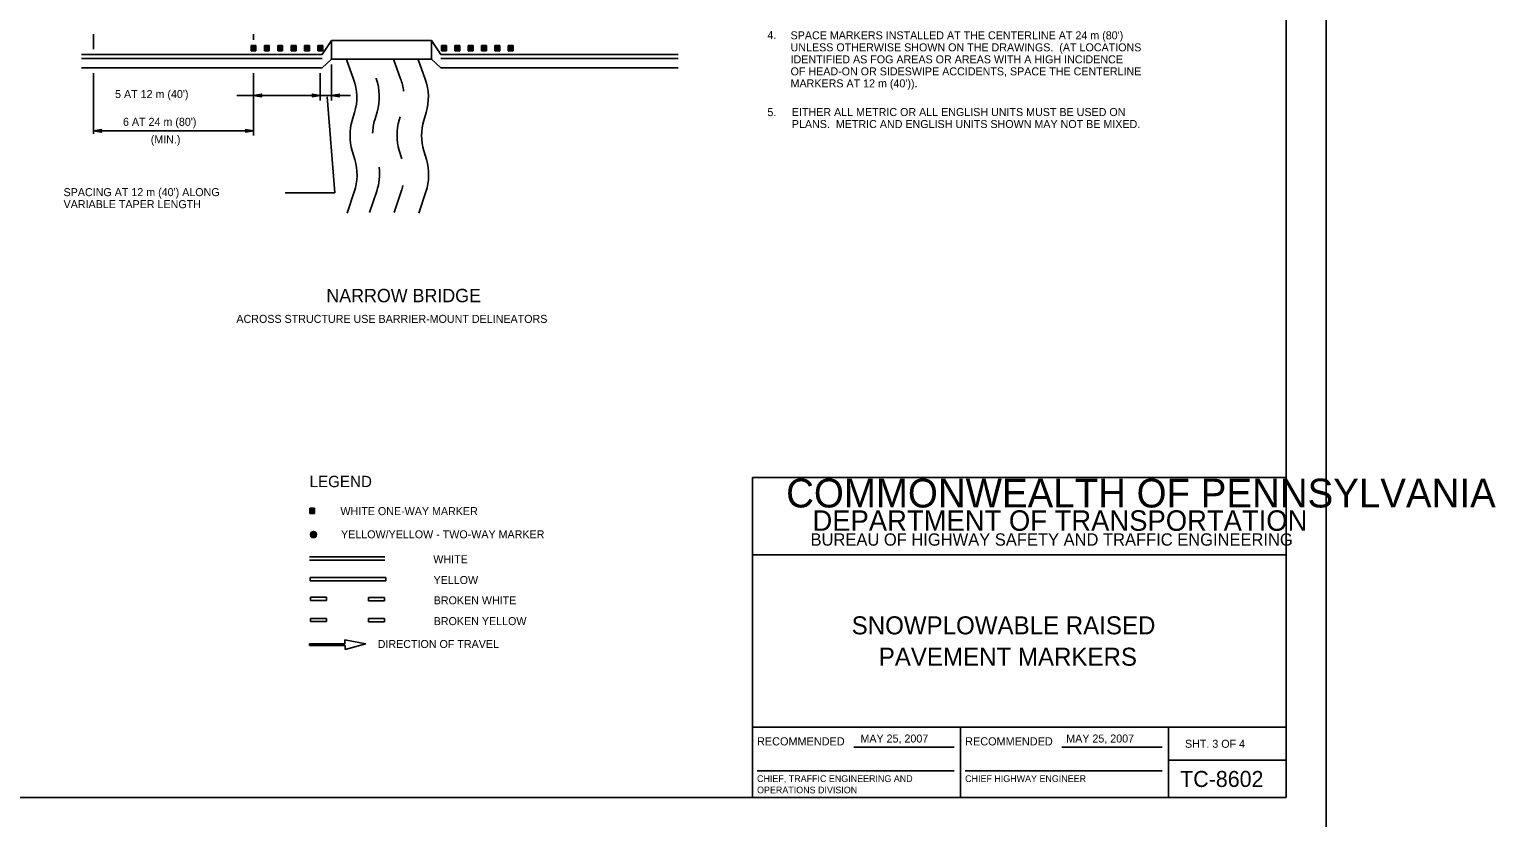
# Model space of a CAD drawing. Extents: x 639362 to 641108, y 298458 to 299646.
# Drawn here: x 640558 to 641108, y 299059 to 299355 of the extents above; entities that cross this region are included whole.
import ezdxf

# ---------------------------------------------------------------- set-up
doc = ezdxf.new("R2010")
doc.units = 0
for name, color, linetype in [('1', 7, 'Continuous'), ('2', 7, 'Continuous'), ('3', 7, 'Continuous'), ('PLT-BNDY', 7, 'Continuous')]:
    doc.layers.add(name, color=color, linetype=linetype)

# ---------------------------------------------------------------- blocks, each defined once
blk = doc.blocks.new('RARROW')
at = {"layer": '3'}
blk.add_lwpolyline([(-2.2695, 0.285), (-2.184875, 0.12075), (0, 0), (-2.2695, 0.285), (-2.38575, 0.384625), (0, 0), (-2.183125, -0.108), (-2.262875, -0.2705), (0, 0), (-2.38575, -0.379125), (-2.262875, -0.2705)], dxfattribs=at)

msp = doc.modelspace()

# ---------------------------------------------------------------- linework, layer by layer
at = {"layer": '1'}
for p, q in [((641029.31, 299066.63), (641029.31, 299630.63)), ((640829.31, 299066.63), (640829.31, 299186.63)), ((640829.31, 299186.63), (641029.31, 299186.63)), ((641029.31, 299157.63), (640829.31, 299157.63)), ((640829.31, 299093), (641029.31, 299093)), ((640907.31, 299093), (640907.31, 299066.63)), ((640985.19, 299066.63), (640985.19, 299093)), ((640867.24, 299085.57), (640904.87, 299085.57)), ((640945.24, 299085.57), (640982.87, 299085.57)), ((640985.19, 299080.63), (641029.31, 299080.63)), ((640830.99, 299076.68), (640904.87, 299076.68)), ((640908.99, 299076.68), (640982.87, 299076.68)), ((641029.31, 299066.63), (640243.31, 299066.63)), ((640243.31, 299066.63), (640829.31, 299066.63))]:
    msp.add_line(p, q, dxfattribs=at)
at = {"layer": '2'}
for p, q in [((640582.27, 299347.07), (640582.27, 299352.76)), ((640641.38, 299348.5), (640643.16, 299348.5)), ((640641.38, 299346.46), (640641.38, 299348.5)), ((640641.56, 299348.32), (640642.98, 299348.32)), ((640641.56, 299346.63), (640641.56, 299348.32)), ((640641.74, 299348.14), (640642.8, 299348.14)), ((640641.74, 299346.81), (640641.74, 299348.14)), ((640641.91, 299346.99), (640641.91, 299347.96)), ((640641.91, 299347.96), (640642.62, 299347.96)), ((640642.09, 299347.79), (640642.45, 299347.79)), ((640642.09, 299347.17), (640642.09, 299347.79)), ((640642.27, 299350.54), (640642.27, 299352.76)), ((640642.27, 299347.61), (640642.27, 299347.34)), ((640642.45, 299347.79), (640642.45, 299347.17)), ((640642.62, 299347.96), (640642.62, 299346.99)), ((640642.8, 299348.14), (640642.8, 299346.81)), ((640642.98, 299348.32), (640642.98, 299346.63)), ((640643.16, 299348.5), (640643.16, 299346.46)), ((640646.38, 299348.5), (640648.16, 299348.5)), ((640646.38, 299346.46), (640646.38, 299348.5)), ((640646.56, 299348.32), (640647.98, 299348.32)), ((640646.56, 299346.63), (640646.56, 299348.32)), ((640646.74, 299348.14), (640647.8, 299348.14)), ((640646.74, 299346.81), (640646.74, 299348.14)), ((640646.91, 299346.99), (640646.91, 299347.96)), ((640646.91, 299347.96), (640647.62, 299347.96)), ((640647.09, 299347.79), (640647.45, 299347.79)), ((640647.09, 299347.17), (640647.09, 299347.79)), ((640647.27, 299347.61), (640647.27, 299347.34)), ((640647.45, 299347.79), (640647.45, 299347.17)), ((640647.62, 299347.96), (640647.62, 299346.99)), ((640647.8, 299348.14), (640647.8, 299346.81)), ((640647.98, 299348.32), (640647.98, 299346.63)), ((640648.16, 299348.5), (640648.16, 299346.46)), ((640651.38, 299348.49), (640653.16, 299348.49)), ((640651.38, 299346.45), (640651.38, 299348.49)), ((640651.56, 299348.32), (640652.98, 299348.32)), ((640651.56, 299346.63), (640651.56, 299348.32)), ((640651.74, 299348.14), (640652.8, 299348.14)), ((640651.74, 299346.81), (640651.74, 299348.14)), ((640651.91, 299346.99), (640651.91, 299347.96)), ((640651.91, 299347.96), (640652.62, 299347.96)), ((640652.09, 299347.79), (640652.45, 299347.79)), ((640652.09, 299347.16), (640652.09, 299347.79)), ((640652.27, 299347.61), (640652.27, 299347.34)), ((640652.45, 299347.79), (640652.45, 299347.16)), ((640652.62, 299347.96), (640652.62, 299346.99)), ((640652.8, 299348.14), (640652.8, 299346.81)), ((640652.98, 299348.32), (640652.98, 299346.63)), ((640653.16, 299348.49), (640653.16, 299346.45)), ((640656.38, 299348.49), (640658.16, 299348.49)), ((640656.38, 299346.45), (640656.38, 299348.49)), ((640656.56, 299348.31), (640657.98, 299348.31)), ((640656.56, 299346.63), (640656.56, 299348.31)), ((640656.74, 299348.14), (640657.8, 299348.14)), ((640656.74, 299346.81), (640656.74, 299348.14)), ((640656.91, 299346.99), (640656.91, 299347.96)), ((640656.91, 299347.96), (640657.62, 299347.96)), ((640657.09, 299347.78), (640657.45, 299347.78)), ((640657.09, 299347.16), (640657.09, 299347.78)), ((640657.27, 299347.61), (640657.27, 299347.34)), ((640657.45, 299347.78), (640657.45, 299347.16)), ((640657.62, 299347.96), (640657.62, 299346.99)), ((640657.8, 299348.14), (640657.8, 299346.81)), ((640657.98, 299348.31), (640657.98, 299346.63)), ((640658.16, 299348.49), (640658.16, 299346.45)), ((640661.38, 299348.49), (640663.16, 299348.49)), ((640661.38, 299346.45), (640661.38, 299348.49)), ((640661.56, 299348.31), (640662.98, 299348.31)), ((640661.56, 299346.63), (640661.56, 299348.31)), ((640661.74, 299348.14), (640662.8, 299348.14)), ((640661.74, 299346.81), (640661.74, 299348.14)), ((640661.91, 299346.98), (640661.91, 299347.96)), ((640661.91, 299347.96), (640662.62, 299347.96)), ((640662.09, 299347.78), (640662.45, 299347.78)), ((640662.09, 299347.16), (640662.09, 299347.78)), ((640662.27, 299347.61), (640662.27, 299347.34)), ((640662.45, 299347.78), (640662.45, 299347.16)), ((640662.62, 299347.96), (640662.62, 299346.98)), ((640662.8, 299348.14), (640662.8, 299346.81)), ((640662.98, 299348.31), (640662.98, 299346.63)), ((640663.16, 299348.49), (640663.16, 299346.45)), ((640666.38, 299348.49), (640668.16, 299348.49)), ((640666.38, 299346.45), (640666.38, 299348.49)), ((640666.56, 299348.31), (640667.98, 299348.31)), ((640666.56, 299346.63), (640666.56, 299348.31)), ((640666.74, 299348.13), (640667.8, 299348.13)), ((640666.74, 299346.81), (640666.74, 299348.13)), ((640666.91, 299346.98), (640666.91, 299347.96)), ((640666.91, 299347.96), (640667.62, 299347.96)), ((640667.09, 299347.78), (640667.45, 299347.78)), ((640667.09, 299347.16), (640667.09, 299347.78)), ((640667.27, 299347.61), (640667.27, 299347.34)), ((640667.45, 299347.78), (640667.45, 299347.16)), ((640667.62, 299347.96), (640667.62, 299346.98)), ((640667.8, 299348.13), (640667.8, 299346.81)), ((640667.94, 299345.07), (640671.45, 299350.34)), ((640667.98, 299348.31), (640667.98, 299346.63)), ((640668.16, 299348.49), (640668.16, 299346.45)), ((640671.45, 299350.34), (640708.95, 299350.34)), ((640671.45, 299350.34), (640671.45, 299343.31)), ((640712.47, 299345.07), (640708.95, 299350.34)), ((640708.95, 299350.34), (640708.95, 299343.31)), ((640712.75, 299348.49), (640714.52, 299348.49)), ((640712.75, 299346.45), (640712.75, 299348.49)), ((640712.92, 299348.31), (640714.34, 299348.31)), ((640712.92, 299346.63), (640712.92, 299348.31)), ((640713.1, 299348.13), (640714.17, 299348.13)), ((640713.1, 299346.81), (640713.1, 299348.13)), ((640713.28, 299346.98), (640713.28, 299347.96)), ((640713.28, 299347.96), (640713.99, 299347.96)), ((640713.46, 299347.78), (640713.81, 299347.78)), ((640713.46, 299347.16), (640713.46, 299347.78)), ((640713.63, 299347.61), (640713.63, 299347.34)), ((640713.81, 299347.78), (640713.81, 299347.16)), ((640713.99, 299347.96), (640713.99, 299346.98)), ((640714.17, 299348.13), (640714.17, 299346.81)), ((640714.34, 299348.31), (640714.34, 299346.63)), ((640714.52, 299348.49), (640714.52, 299346.45)), ((640717.75, 299348.49), (640719.52, 299348.49)), ((640717.75, 299346.45), (640717.75, 299348.49)), ((640717.92, 299348.31), (640719.34, 299348.31)), ((640717.92, 299346.63), (640717.92, 299348.31)), ((640718.1, 299348.13), (640719.17, 299348.13)), ((640718.1, 299346.81), (640718.1, 299348.13)), ((640718.28, 299346.98), (640718.28, 299347.96)), ((640718.28, 299347.96), (640718.99, 299347.96)), ((640718.46, 299347.78), (640718.81, 299347.78)), ((640718.46, 299347.16), (640718.46, 299347.78)), ((640718.63, 299347.6), (640718.63, 299347.34)), ((640718.81, 299347.78), (640718.81, 299347.16)), ((640718.99, 299347.96), (640718.99, 299346.98)), ((640719.17, 299348.13), (640719.17, 299346.81)), ((640719.34, 299348.31), (640719.34, 299346.63)), ((640719.52, 299348.49), (640719.52, 299346.45)), ((640722.75, 299348.49), (640724.52, 299348.49)), ((640722.75, 299346.45), (640722.75, 299348.49)), ((640722.92, 299348.31), (640724.34, 299348.31)), ((640722.92, 299346.63), (640722.92, 299348.31)), ((640723.1, 299348.13), (640724.17, 299348.13)), ((640723.1, 299346.8), (640723.1, 299348.13)), ((640723.28, 299346.98), (640723.28, 299347.96)), ((640723.28, 299347.96), (640723.99, 299347.96)), ((640723.46, 299347.78), (640723.81, 299347.78)), ((640723.46, 299347.16), (640723.46, 299347.78)), ((640723.63, 299347.6), (640723.63, 299347.33)), ((640723.81, 299347.78), (640723.81, 299347.16)), ((640723.99, 299347.96), (640723.99, 299346.98)), ((640724.17, 299348.13), (640724.17, 299346.8)), ((640724.34, 299348.31), (640724.34, 299346.63)), ((640724.52, 299348.49), (640724.52, 299346.45)), ((640727.75, 299348.49), (640729.52, 299348.49)), ((640727.75, 299346.45), (640727.75, 299348.49)), ((640727.92, 299348.31), (640729.34, 299348.31)), ((640727.92, 299346.62), (640727.92, 299348.31)), ((640728.1, 299348.13), (640729.17, 299348.13)), ((640728.1, 299346.8), (640728.1, 299348.13)), ((640728.28, 299346.98), (640728.28, 299347.95)), ((640728.28, 299347.95), (640728.99, 299347.95)), ((640728.46, 299347.78), (640728.81, 299347.78)), ((640728.46, 299347.16), (640728.46, 299347.78)), ((640728.63, 299347.6), (640728.63, 299347.33)), ((640728.81, 299347.78), (640728.81, 299347.16)), ((640728.99, 299347.95), (640728.99, 299346.98)), ((640729.17, 299348.13), (640729.17, 299346.8)), ((640729.34, 299348.31), (640729.34, 299346.62)), ((640729.52, 299348.49), (640729.52, 299346.45)), ((640732.75, 299348.49), (640734.52, 299348.49)), ((640732.75, 299346.45), (640732.75, 299348.49)), ((640732.92, 299348.31), (640734.34, 299348.31)), ((640732.92, 299346.62), (640732.92, 299348.31)), ((640733.1, 299348.13), (640734.17, 299348.13)), ((640733.1, 299346.8), (640733.1, 299348.13)), ((640733.28, 299346.98), (640733.28, 299347.95)), ((640733.28, 299347.95), (640733.99, 299347.95)), ((640733.46, 299347.78), (640733.81, 299347.78)), ((640733.46, 299347.16), (640733.46, 299347.78)), ((640733.63, 299347.6), (640733.63, 299347.33)), ((640733.81, 299347.78), (640733.81, 299347.16)), ((640733.99, 299347.95), (640733.99, 299346.98)), ((640734.17, 299348.13), (640734.17, 299346.8)), ((640734.34, 299348.31), (640734.34, 299346.62)), ((640734.52, 299348.49), (640734.52, 299346.45)), ((640737.75, 299348.48), (640739.52, 299348.48)), ((640737.75, 299346.44), (640737.75, 299348.48)), ((640737.92, 299348.31), (640739.34, 299348.31)), ((640737.92, 299346.62), (640737.92, 299348.31)), ((640738.1, 299348.13), (640739.17, 299348.13)), ((640738.1, 299346.8), (640738.1, 299348.13)), ((640738.28, 299346.98), (640738.28, 299347.95)), ((640738.28, 299347.95), (640738.99, 299347.95)), ((640738.46, 299347.78), (640738.81, 299347.78)), ((640738.46, 299347.15), (640738.46, 299347.78)), ((640738.63, 299347.6), (640738.63, 299347.33)), ((640738.81, 299347.78), (640738.81, 299347.15)), ((640738.99, 299347.95), (640738.99, 299346.98)), ((640739.17, 299348.13), (640739.17, 299346.8)), ((640739.34, 299348.31), (640739.34, 299346.62)), ((640739.52, 299348.48), (640739.52, 299346.44)), ((640577.74, 299345.07), (640667.94, 299345.07)), ((640577.74, 299343.57), (640667.94, 299343.57)), ((640643.16, 299346.46), (640641.38, 299346.46)), ((640642.98, 299346.63), (640641.56, 299346.63)), ((640642.8, 299346.81), (640641.74, 299346.81)), ((640642.62, 299346.99), (640641.91, 299346.99)), ((640642.45, 299347.17), (640642.09, 299347.17)), ((640648.16, 299346.46), (640646.38, 299346.46)), ((640647.98, 299346.63), (640646.56, 299346.63)), ((640647.8, 299346.81), (640646.74, 299346.81)), ((640647.62, 299346.99), (640646.91, 299346.99)), ((640647.45, 299347.17), (640647.09, 299347.17)), ((640653.16, 299346.45), (640651.38, 299346.45)), ((640652.98, 299346.63), (640651.56, 299346.63)), ((640652.8, 299346.81), (640651.74, 299346.81)), ((640652.62, 299346.99), (640651.91, 299346.99)), ((640652.45, 299347.16), (640652.09, 299347.16)), ((640658.16, 299346.45), (640656.38, 299346.45)), ((640657.98, 299346.63), (640656.56, 299346.63)), ((640657.8, 299346.81), (640656.74, 299346.81)), ((640657.62, 299346.99), (640656.91, 299346.99)), ((640657.45, 299347.16), (640657.09, 299347.16)), ((640663.16, 299346.45), (640661.38, 299346.45)), ((640662.98, 299346.63), (640661.56, 299346.63)), ((640662.8, 299346.81), (640661.74, 299346.81)), ((640662.62, 299346.98), (640661.91, 299346.98)), ((640662.45, 299347.16), (640662.09, 299347.16)), ((640668.16, 299346.45), (640666.38, 299346.45)), ((640667.98, 299346.63), (640666.56, 299346.63)), ((640667.8, 299346.81), (640666.74, 299346.81)), ((640667.62, 299346.98), (640666.91, 299346.98)), ((640667.45, 299347.16), (640667.09, 299347.16)), ((640667.94, 299340.07), (640671.45, 299343.31)), ((640671.45, 299343.31), (640708.95, 299343.31)), ((640679.74, 299335.87), (640677.07, 299343.23)), ((640697.39, 299336.02), (640694.71, 299343.37)), ((640706.59, 299335.87), (640703.91, 299343.23)), ((640712.47, 299340.07), (640708.95, 299343.31)), ((640712.47, 299345.07), (640801.44, 299345.07)), ((640712.47, 299343.57), (640801.44, 299343.57)), ((640714.52, 299346.45), (640712.75, 299346.45)), ((640714.34, 299346.63), (640712.92, 299346.63)), ((640714.17, 299346.81), (640713.1, 299346.81)), ((640713.99, 299346.98), (640713.28, 299346.98)), ((640713.81, 299347.16), (640713.46, 299347.16)), ((640719.52, 299346.45), (640717.75, 299346.45)), ((640719.34, 299346.63), (640717.92, 299346.63)), ((640719.17, 299346.81), (640718.1, 299346.81)), ((640718.99, 299346.98), (640718.28, 299346.98)), ((640718.81, 299347.16), (640718.46, 299347.16)), ((640724.52, 299346.45), (640722.75, 299346.45)), ((640724.34, 299346.63), (640722.92, 299346.63)), ((640724.17, 299346.8), (640723.1, 299346.8)), ((640723.99, 299346.98), (640723.28, 299346.98)), ((640723.81, 299347.16), (640723.46, 299347.16)), ((640729.52, 299346.45), (640727.75, 299346.45)), ((640729.34, 299346.62), (640727.92, 299346.62)), ((640729.17, 299346.8), (640728.1, 299346.8)), ((640728.99, 299346.98), (640728.28, 299346.98)), ((640728.81, 299347.16), (640728.46, 299347.16)), ((640734.52, 299346.45), (640732.75, 299346.45)), ((640734.34, 299346.62), (640732.92, 299346.62)), ((640734.17, 299346.8), (640733.1, 299346.8)), ((640733.99, 299346.98), (640733.28, 299346.98)), ((640733.81, 299347.16), (640733.46, 299347.16)), ((640739.52, 299346.44), (640737.75, 299346.44)), ((640739.34, 299346.62), (640737.92, 299346.62)), ((640739.17, 299346.8), (640738.1, 299346.8)), ((640738.99, 299346.98), (640738.28, 299346.98)), ((640738.81, 299347.15), (640738.46, 299347.15)), ((640577.74, 299340.07), (640667.94, 299340.07)), ((640582.26, 299315.37), (640582.26, 299338.07)), ((640642.26, 299314.79), (640642.26, 299338.07)), ((640667.26, 299327.81), (640667.26, 299338.07)), ((640671.45, 299327.8), (640671.45, 299341.31)), ((640712.47, 299340.07), (640801.44, 299340.07)), ((640688.19, 299336.08), (640688.16, 299336.16)), ((640667.26, 299329.77), (640635.98, 299329.77)), ((640678.56, 299329.77), (640667.26, 299329.77)), ((640672.76, 299293.3), (640669.79, 299329.18)), ((640679.24, 299320.39), (640680.12, 299323.32)), ((640687.68, 299320.6), (640688.56, 299323.54)), ((640696.89, 299320.54), (640697.23, 299321.69)), ((640706.09, 299320.39), (640706.96, 299323.32)), ((640642.26, 299316.45), (640582.26, 299316.46)), ((640680.21, 299305.72), (640679.23, 299309)), ((640697.82, 299305.96), (640696.88, 299309.14)), ((640707.05, 299305.72), (640706.08, 299309)), ((640672.76, 299293.3), (640654.16, 299293.3)), ((640677.31, 299285.68), (640679.99, 299293.67)), ((640685.75, 299285.9), (640688.43, 299293.88)), ((640694.95, 299285.83), (640697.63, 299293.81)), ((640704.15, 299285.68), (640706.83, 299293.67)), ((640663.35, 299175.09), (640665.13, 299175.09)), ((640663.35, 299173.05), (640663.35, 299175.09)), ((640665.13, 299173.05), (640663.35, 299173.05)), ((640663.53, 299174.91), (640664.95, 299174.91)), ((640663.53, 299173.22), (640663.53, 299174.91)), ((640664.95, 299173.22), (640663.53, 299173.22)), ((640663.71, 299174.73), (640664.77, 299174.73)), ((640663.71, 299173.4), (640663.71, 299174.73)), ((640664.77, 299173.4), (640663.71, 299173.4)), ((640663.89, 299173.58), (640663.89, 299174.55)), ((640663.89, 299174.55), (640664.59, 299174.55)), ((640664.59, 299173.58), (640663.89, 299173.58)), ((640664.06, 299174.38), (640664.42, 299174.38)), ((640664.06, 299173.76), (640664.06, 299174.38)), ((640664.42, 299173.76), (640664.06, 299173.76)), ((640664.24, 299174.2), (640664.24, 299173.93)), ((640664.42, 299174.38), (640664.42, 299173.76)), ((640664.59, 299174.55), (640664.59, 299173.58)), ((640664.77, 299174.73), (640664.77, 299173.4)), ((640664.95, 299174.91), (640664.95, 299173.22)), ((640665.13, 299175.09), (640665.13, 299173.05)), ((640691.51, 299156.85), (640663.23, 299156.85)), ((640691.51, 299155.65), (640663.23, 299155.65)), ((640691.78, 299149.09), (640663.5, 299149.09)), ((640663.5, 299149.09), (640663.5, 299147.89)), ((640663.5, 299147.89), (640691.78, 299147.89)), ((640691.78, 299147.89), (640691.78, 299149.09)), ((640669.6, 299141.71), (640663.58, 299141.71)), ((640663.58, 299141.71), (640663.58, 299140.51)), ((640663.58, 299140.51), (640669.6, 299140.51)), ((640669.6, 299140.51), (640669.6, 299141.71)), ((640691.32, 299141.61), (640685.3, 299141.61)), ((640685.3, 299141.61), (640685.3, 299140.41)), ((640685.3, 299140.41), (640691.32, 299140.41)), ((640691.32, 299140.41), (640691.32, 299141.61)), ((640663.61, 299133.81), (640663.61, 299132.61)), ((640669.62, 299133.81), (640663.61, 299133.81)), ((640669.62, 299132.61), (640669.62, 299133.81)), ((640685.33, 299133.71), (640685.33, 299132.51)), ((640691.34, 299133.71), (640685.33, 299133.71)), ((640691.34, 299132.51), (640691.34, 299133.71)), ((640663.61, 299132.61), (640669.62, 299132.61)), ((640685.33, 299132.51), (640691.34, 299132.51)), ((640676.5, 299124.3), (640663.26, 299124.3)), ((640663.26, 299124.3), (640663.26, 299123.59)), ((640663.26, 299123.59), (640676.58, 299123.59)), ((640684.31, 299124.26), (640676.5, 299125.74)), ((640676.5, 299125.74), (640676.5, 299124.3)), ((640676.58, 299122.15), (640684.31, 299124.26)), ((640676.58, 299123.59), (640676.58, 299122.15))]:
    msp.add_line(p, q, dxfattribs=at)
for radius in [1.15, 1.07, 0.985, 0.904, 0.822, 0.741, 0.659, 0.578, 0.496, 0.414, 0.333, 0.251, 0.17, 0.0881]:
    msp.add_circle((640664.72, 299165.21), radius, dxfattribs=at)
for centre, start, end in [((640660.95, 299329.03), 343.4142, 19.9879), ((640669.39, 299329.25), 343.4142, 19.9879), ((640678.59, 299329.18), 6.1927, 19.9879), ((640687.79, 299329.03), 343.4142, 19.9879), ((640698.41, 299314.68), 163.4142, 196.5084), ((640706.85, 299314.89), 163.4142, 177.785), ((640716.05, 299314.83), 163.4142, 196.5084), ((640725.26, 299314.68), 163.4142, 196.5084), ((640661.03, 299300.04), 341.4259, 16.5084), ((640687.88, 299300.04), 341.4259, 16.5084), ((640669.47, 299300.25), 341.4259, 7.3864), ((640678.67, 299300.18), 341.4259, 347.8196)]:
    msp.add_arc(centre, 20, start, end, dxfattribs=at)
at = {"layer": 'PLT-BNDY'}
msp.add_lwpolyline([(640203.31, 299645.63), (641044.31, 299645.63), (641044.31, 299051.63), (640203.31, 299051.63)], close=True, dxfattribs=at)

# ---------------------------------------------------------------- block references
at = {"layer": '2', "xscale": 1.2574347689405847, "yscale": 1.3092961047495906, "rotation": 180}
for p in [(640642.26, 299329.77), (640671.45, 299329.77), (640582.26, 299316.46)]:
    msp.add_blockref('RARROW', p, dxfattribs=at)
at = {"layer": '2', "xscale": 1.2574347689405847, "yscale": 1.3092961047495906}
for p in [(640667.26, 299329.77), (640642.26, 299316.45)]:
    msp.add_blockref('RARROW', p, dxfattribs=at)

# ---------------------------------------------------------------- texts
at = {"layer": '1'}
for s, height, p in [('COMMONWEALTH OF PENNSYLVANIA', 10.7828, (640841.9, 299175.36)), ('DEPARTMENT OF TRANSPORTATION', 7.6837, (640851.76, 299166.61)), ('BUREAU OF HIGHWAY SAFETY AND TRAFFIC ENGINEERING', 4.6253, (640851.04, 299161.04)), ('SNOWPLOWABLE RAISED', 6.75, (640866.46, 299127.81)), ('PAVEMENT MARKERS', 6.75, (640876.61, 299116.06)), ('RECOMMENDED', 3.048, (640830.99, 299086.2)), ('RECOMMENDED', 3.048, (640908.99, 299086.2)), ('SHT. 3 OF 4', 3, (640991.4, 299085.31)), ('CHIEF, TRAFFIC ENGINEERING AND', 2.5, (640830.99, 299072.51)), ('CHIEF HIGHWAY ENGINEER', 2.5, (640908.99, 299072.51)), ('TC-8602', 6, (640989.6, 299070.63)), ('OPERATIONS DIVISION', 2.5, (640830.99, 299068.26))]:
    msp.add_text(s, height=height, dxfattribs=at).set_placement(p)
at = {"layer": '2'}
for s, height, p in [('4. ', 3, (640834.87, 299350.89)), ("SPACE MARKERS INSTALLED AT THE CENTERLINE AT 24 m (80')", 3, (640843.55, 299350.77)), ('UNLESS OTHERWISE SHOWN ON THE DRAWINGS.  (AT LOCATIONS', 3, (640843.55, 299346.27)), ('IDENTIFIED AS FOG AREAS OR AREAS WITH A HIGH INCIDENCE', 3, (640843.55, 299341.77)), ('OF HEAD-ON OR SIDESWIPE ACCIDENTS, SPACE THE CENTERLINE', 3, (640843.55, 299337.27)), ("5 AT 12 m (40')", 3, (640590.34, 299328.76)), ("MARKERS AT 12 m (40')).", 3, (640843.55, 299332.77)), ("6 AT 24 m (80')", 3, (640593.31, 299318.36)), ('5. ', 3, (640834.87, 299322)), ('EITHER ALL METRIC OR ALL ENGLISH UNITS MUST BE USED ON', 3, (640844.02, 299322.03)), ('PLANS.  METRIC AND ENGLISH UNITS SHOWN MAY NOT BE MIXED.', 3, (640844.02, 299317.53)), (' (MIN.)', 3, (640602.6, 299311.77)), ("SPACING AT 12 m (40') ALONG", 3, (640571.03, 299292.01)), ('VARIABLE TAPER LENGTH', 3, (640571.03, 299287.51)), ('NARROW BRIDGE', 5, (640669.54, 299252.27)), ('ACROSS STRUCTURE USE BARRIER-MOUNT DELINEATORS', 3, (640635.82, 299244.52)), ('LEGEND', 4.25, (640663.25, 299182.97)), ('WHITE ONE-WAY MARKER', 3, (640674.83, 299172.49)), ('YELLOW/YELLOW - TWO-WAY MARKER', 3, (640675.04, 299163.8)), ('WHITE', 3, (640709.63, 299154.47)), ('YELLOW', 3, (640709.71, 299146.67)), ('BROKEN WHITE', 3, (640709.78, 299139.06)), ('BROKEN YELLOW', 3, (640709.78, 299131.27)), ('DIRECTION OF TRAVEL', 3, (640688.78, 299122.7)), ('MAY 25, 2007', 3, (640869.74, 299087.28)), ('MAY 25, 2007', 3, (640946.89, 299087.28))]:
    msp.add_text(s, height=height, dxfattribs=at).set_placement(p)

doc.saveas('drawing.dxf')
